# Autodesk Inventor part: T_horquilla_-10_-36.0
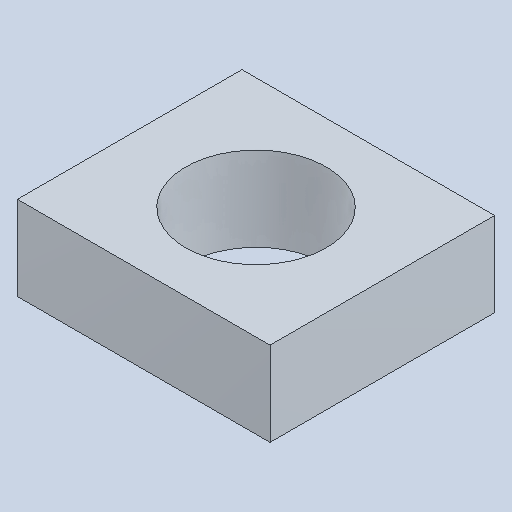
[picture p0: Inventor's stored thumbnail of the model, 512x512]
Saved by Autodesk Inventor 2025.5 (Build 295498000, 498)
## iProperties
Created: 2026-10
Part Number: T_horquilla_-10_-36.0
Material: Genérico
Document SubType Name: Modeling
Designer: Luis M
Density: 1 g/cm^3
Appearance: Valor por defecto
Author: Luis M
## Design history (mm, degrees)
feature "Base1"
node "Sólido1"
